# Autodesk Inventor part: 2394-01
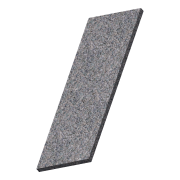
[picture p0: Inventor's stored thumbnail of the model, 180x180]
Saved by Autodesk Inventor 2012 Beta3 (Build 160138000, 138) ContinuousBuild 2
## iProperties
Created: 2011-02
Part Number: 2394-01
Material: Default
Document SubType Name: Modeling
Designer: Beta-8540w
Density: 1 g/cm^3
bottom_thickness: 0.250 in
Author: Beta-8540w
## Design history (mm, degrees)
derived "c15-11.ipt" dims "d2" = 15.875, "d3" = 0, "d4" = 4.4958, "d12" = 4.4958, "d22" = 6.35, "d23" = 0, "d24" = 9.652, "d26" = 6.35, "d27" = 0, "d72" = 19.05, "d73" = 19.05, "d74" = 3.302, "d75" = 3.302, "d76" = 12.7, "drawer_width" = 609.6, "drawer_height" = 203.2, "dbl_pull_width" = 101.6, "back_width" = 546.1, "bottom_thickness" = 6.35
body "Solid1"
feature "Solid1::c15-11.ipt" dims "d2" = 15.875, "d3" = 0, "d4" = 4.4958, "d12" = 4.4958, "d22" = 6.35, "d23" = 0, "d24" = 9.652, "d26" = 6.35, "d27" = 0, "d72" = 19.05, "d73" = 19.05, "d74" = 3.302, "d75" = 3.302, "d76" = 12.7, "drawer_width" = 609.6, "drawer_height" = 203.2, "dbl_pull_width" = 101.6, "back_width" = 546.1, "bottom_thickness" = 6.35, "ScaleForDerivedMember" = 10
tag "TaggingFeature1"
